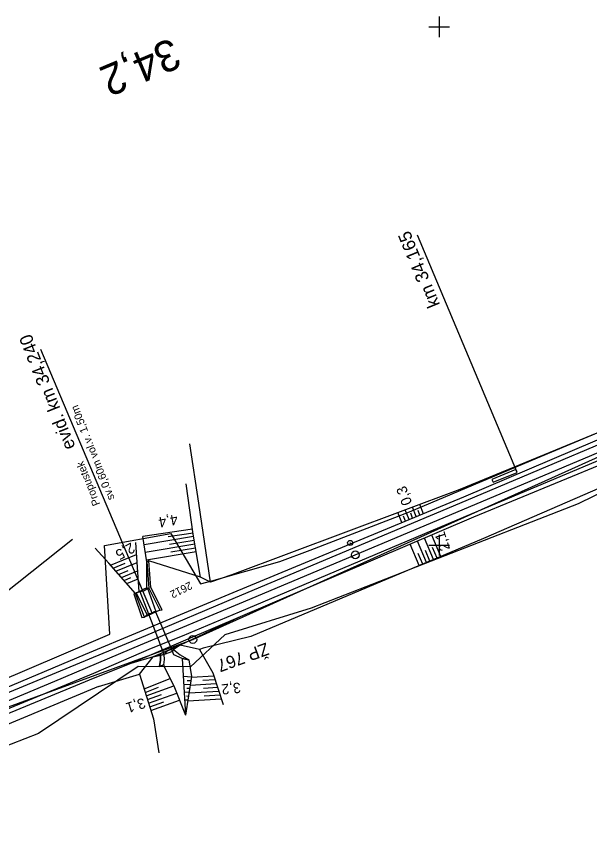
# Model space of a CAD drawing. Extents: x -805730 to -804640, y -1150889 to -1150366.
# Drawn here: x -805081.6 to -804971, y -1150657.1 to -1150498 of the extents above; entities that cross this region are included whole.
import ezdxf

# ---------------------------------------------------------------- set-up
doc = ezdxf.new("R2010")
doc.units = 0
for name, color, linetype in [('0381KM032-037P - Vrstva 1', 7, 'Continuous'), ('0381KM032-037P - Vrstva 16', 7, 'Continuous'), ('0381KM032-037P - Vrstva 17', 7, 'Continuous'), ('0381KM032-037P - Vrstva 19', 7, 'Continuous'), ('0381KM032-037P - Vrstva 4', 7, 'Continuous'), ('0381KM032-037P - Vrstva 48', 7, 'Continuous'), ('0381KM032-037P - Vrstva 49', 7, 'Continuous'), ('0381KM032-037P - Vrstva 57', 7, 'Continuous'), ('0381KM032-037P - Vrstva 7', 7, 'Continuous'), ('0381KM032-037P - Vrstva 9', 7, 'Continuous'), ('hran DP - hran DP', 7, 'Continuous'), ('krizky_1000 - Vrstva 1', 7, 'Continuous'), ('vyt_sit - polygon', 7, 'Continuous'), ('vyt_sit - stávající', 7, 'Continuous')]:
    doc.layers.add(name, color=color, linetype=linetype)

msp = doc.modelspace()

# ---------------------------------------------------------------- linework, layer by layer
at = {"layer": '0381KM032-037P - Vrstva 1'}
for points in [[(-804910.33, -1150557.31), (-804952.12, -1150574.92), (-804994.42, -1150592.71), (-805038.63, -1150611.27), (-805057.71, -1150619.3), (-805074.24, -1150626.27)], [(-805074.24, -1150626.27), (-805091.51, -1150633.48)]]:
    msp.add_lwpolyline(points, dxfattribs=at)
at = {"layer": '0381KM032-037P - Vrstva 16'}
for points in [[(-805053.78, -1150621.21), (-805053.78, -1150622.18), (-805053.99, -1150623.39), (-805053.13, -1150623.09), (-805053, -1150622.04), (-805053.1, -1150621.07), (-805053.78, -1150621.21)], [(-805051.5, -1150620.47), (-805051.28, -1150620.09), (-805050.01, -1150621.11), (-805048.33, -1150622.13), (-805049.58, -1150621.86), (-805051.2, -1150621.14), (-805051.5, -1150620.47)]]:
    msp.add_lwpolyline(points, dxfattribs=at)
at = {"layer": '0381KM032-037P - Vrstva 17'}
for points in [[(-804868.16, -1150549.89), (-804869.02, -1150549.09), (-804889.78, -1150557.12), (-804908.89, -1150563.18), (-804949.8, -1150580.61), (-804991.45, -1150598.69), (-805036.34, -1150617.58)], [(-804906.51, -1150551), (-804923.2, -1150557.6), (-804942.52, -1150566.83), (-804953.3, -1150571.71), (-804995.99, -1150589.23), (-805040.03, -1150605.68), (-805044.15, -1150607.13)], [(-805044.15, -1150607.13), (-805046.42, -1150591.86), (-805048.16, -1150580.41)], [(-805070.8, -1150598.9), (-805121.06, -1150638.84), (-805152.76, -1150646.7), (-805170.92, -1150650.08), (-805194.39, -1150650.05), (-805213.2, -1150651.26), (-805221.79, -1150652.33), (-805228.79, -1150654.03)]]:
    msp.add_lwpolyline(points, dxfattribs=at)
at = {"layer": '0381KM032-037P - Vrstva 19'}
for p, q in [((-805076.95, -1150562.18), (-805055.39, -1150613.19)), ((-805056.34, -1150613.34), (-805058.5, -1150609.19)), ((-805054.78, -1150612.85), (-805056.06, -1150613.31)), ((-805053.1, -1150621.07), (-805056.06, -1150613.31)), ((-805054.78, -1150612.85), (-805051.5, -1150620.47)), ((-805051.5, -1150620.47), (-805053.1, -1150621.07))]:
    msp.add_line(p, q, dxfattribs=at)
for points in [[(-805056.22, -1150608.31), (-805056.45, -1150608.2), (-805056.44, -1150603.21)], [(-805053.89, -1150612.54), (-805053.47, -1150612.44), (-805055.64, -1150608.13), (-805056.05, -1150602.98), (-805056.44, -1150603.21), (-805056.02, -1150608.26)], [(-805056.45, -1150608.2), (-805056.99, -1150608.48), (-805057.93, -1150608.98), (-805058.5, -1150609.19)], [(-805054.6, -1150612.84), (-805056.22, -1150608.31), (-805056.92, -1150608.82), (-805057.71, -1150609)], [(-805056.22, -1150608.31), (-805056.02, -1150608.26), (-805053.89, -1150612.54), (-805056.9, -1150613.84)], [(-805056.06, -1150613.31), (-805057.71, -1150609), (-805058.5, -1150609.19), (-805058.59, -1150609.33), (-805058.96, -1150609.37), (-805057.41, -1150613.95), (-805056.9, -1150613.84), (-805058.59, -1150609.33)], [(-805055.86, -1150613.18), (-805056.06, -1150613.31), (-805056.34, -1150613.34), (-805056.9, -1150613.84)], [(-805054.6, -1150612.84), (-805054.78, -1150612.85), (-805055.1, -1150612.83)], [(-805055.21, -1150621.51), (-805053.78, -1150621.21), (-805055.21, -1150621.51), (-805050.01, -1150619.25), (-805051.28, -1150620.09), (-805051.5, -1150620.47), (-805051.69, -1150620.12)], [(-805053.78, -1150621.21), (-805053.1, -1150621.07), (-805052.93, -1150620.83)]]:
    msp.add_lwpolyline(points, dxfattribs=at)
for centre, major_axis, ratio, start_param, end_param in [((-805055.48, -1150613.01), (0.389, 0.172), 0.155868, 3.060843, 6.493994), ((-805052.24, -1150620.62), (-0.751, -0.434), 0.315901, 3.723079, 5.657425)]:
    msp.add_ellipse(centre, major_axis=major_axis, ratio=ratio, start_param=start_param, end_param=end_param, dxfattribs=at)
at = {"layer": '0381KM032-037P - Vrstva 4'}
for points in [[(-804864.42, -1150538.53), (-804893.06, -1150548.77), (-804911.6, -1150556.2), (-804952.82, -1150573.68), (-804994.86, -1150591.44), (-805039.39, -1150610.13), (-805056.71, -1150617.44), (-805097.6, -1150634.39)], [(-804872.17, -1150539.66), (-804893.72, -1150547.52), (-804911.96, -1150555), (-804952.93, -1150572.63), (-804995.29, -1150590.69), (-805039.86, -1150609.18), (-805057.83, -1150616.69), (-805068.36, -1150621.07), (-805097.92, -1150633.57)], [(-804862.73, -1150542.41), (-804863.39, -1150541.46), (-804892.29, -1150551.48), (-804910.22, -1150558.86), (-804951.61, -1150576.23), (-804993.7, -1150593.96), (-805038.63, -1150612.92), (-805049.62, -1150617.53), (-805055.59, -1150619.94), (-805066.74, -1150624.75), (-805096.44, -1150637.01)], [(-804864.94, -1150543.15), (-804869.59, -1150544.8), (-804891.93, -1150552.26), (-804909.8, -1150559.87), (-804951.24, -1150577.2), (-804993.38, -1150594.6), (-805038.39, -1150613.8), (-805059.54, -1150622.79), (-805066.49, -1150625.57), (-805096.25, -1150637.87)]]:
    msp.add_lwpolyline(points, dxfattribs=at)
at = {"layer": '0381KM032-037P - Vrstva 48'}
for p, q in [((-805004.43, -1150594.48), (-805005.15, -1150592.66)), ((-805003.04, -1150593.91), (-805003.74, -1150592.13)), ((-805007.2, -1150595.63), (-805007.96, -1150593.7)), ((-805006.51, -1150595.34), (-805006.88, -1150594.39)), ((-805005.82, -1150595.05), (-805006.56, -1150593.18)), ((-805005.12, -1150594.77), (-805005.49, -1150593.84)), ((-805003.74, -1150594.19), (-805004.09, -1150593.29)), ((-805047.61, -1150596.92), (-805057.19, -1150598.31)), ((-805047.4, -1150598.32), (-805056.95, -1150599.89)), ((-805047.5, -1150597.67), (-805052.29, -1150598.36)), ((-805047.27, -1150599.06), (-805052.05, -1150599.84)), ((-805002.47, -1150603.33), (-805004.21, -1150599.21)), ((-805001.09, -1150602.75), (-805002.83, -1150598.63)), ((-804999.71, -1150602.17), (-805001.45, -1150598.04)), ((-805047.15, -1150599.8), (-805056.72, -1150601.37)), ((-805047.02, -1150600.54), (-805051.82, -1150601.32)), ((-805003.86, -1150603.91), (-805005.59, -1150599.8)), ((-805000.4, -1150602.46), (-805001.27, -1150600.4)), ((-805063.45, -1150603.82), (-805058.4, -1150601.75)), ((-805046.9, -1150601.28), (-805056.5, -1150602.85)), ((-805003.17, -1150603.62), (-805004.03, -1150601.56)), ((-805001.78, -1150603.04), (-805002.65, -1150600.98)), ((-805062.93, -1150604.42), (-805060.64, -1150603.48)), ((-805062.4, -1150605.02), (-805058.3, -1150603.33)), ((-805061.88, -1150605.61), (-805060.06, -1150604.86)), ((-805061.35, -1150606.21), (-805058.2, -1150604.91)), ((-805060.83, -1150606.8), (-805059.49, -1150606.25)), ((-805060.3, -1150607.4), (-805058.09, -1150606.49)), ((-805056.95, -1150627.71), (-805051.95, -1150625.67)), ((-805047.79, -1150625.42), (-805049.38, -1150625.34)), ((-805047.91, -1150626.17), (-805048.62, -1150626.13)), ((-805043.49, -1150625.24), (-805047.8, -1150625.5)), ((-805043.25, -1150625.97), (-805045.59, -1150626.11)), ((-805056.72, -1150628.43), (-805054.17, -1150627.38)), ((-805056.53, -1150629.02), (-805051.22, -1150627.12)), ((-805048.02, -1150626.91), (-805049.29, -1150626.85)), ((-805048.14, -1150627.66), (-805048.69, -1150627.63)), ((-805043.02, -1150626.71), (-805048.04, -1150627.02)), ((-805042.78, -1150627.45), (-805045.47, -1150627.61)), ((-805056.31, -1150629.74), (-805053.62, -1150628.78)), ((-805056.08, -1150630.46), (-805050.66, -1150628.52)), ((-805048.26, -1150628.4), (-805049.2, -1150628.36)), ((-805048.37, -1150629.15), (-805048.77, -1150629.13)), ((-805042.54, -1150628.18), (-805048.28, -1150628.53)), ((-805042.3, -1150628.92), (-805045.35, -1150629.11)), ((-805055.86, -1150631.17), (-805053.12, -1150630.19)), ((-805055.63, -1150631.89), (-805050.1, -1150629.91)), ((-805048.49, -1150629.89), (-805049.11, -1150629.86)), ((-805042.06, -1150629.66), (-805048.51, -1150630.05))]:
    msp.add_line(p, q, dxfattribs=at)
at = {"layer": '0381KM032-037P - Vrstva 49'}
for p, q in [((-805056.44, -1150603.21), (-805057.2, -1150598.28)), ((-805057.93, -1150608.98), (-805058.55, -1150599.44)), ((-805056.05, -1150602.98), (-805056.44, -1150603.21)), ((-805044.15, -1150607.13), (-805046.07, -1150606.17)), ((-805049.58, -1150621.86), (-805048.94, -1150632.8)), ((-805049.58, -1150621.86), (-805048.33, -1150622.13))]:
    msp.add_line(p, q, dxfattribs=at)
for points in [[(-804871.36, -1150538.86), (-804872.17, -1150539.66), (-804893.72, -1150547.52), (-804911.96, -1150555), (-804952.93, -1150572.63), (-804995.29, -1150590.69), (-805039.86, -1150609.18), (-805057.83, -1150616.69), (-805068.36, -1150621.07), (-805097.92, -1150633.57)], [(-804906.51, -1150551), (-804923.2, -1150557.6), (-804942.52, -1150566.83), (-804953.3, -1150571.71), (-804995.99, -1150589.23), (-805040.03, -1150605.68), (-805044.15, -1150607.13)], [(-804889.78, -1150557.12), (-804908.89, -1150563.18), (-804949.8, -1150580.61), (-804991.45, -1150598.69), (-805036.34, -1150617.58)], [(-804909.8, -1150559.87), (-804951.24, -1150577.2), (-804993.38, -1150594.6), (-805038.39, -1150613.8), (-805050.01, -1150619.25), (-805055.21, -1150621.51), (-805059.54, -1150622.79), (-805066.49, -1150625.57), (-805096.25, -1150637.87)], [(-805046.07, -1150606.17), (-805047.47, -1150597.89), (-805048.87, -1150588.15)], [(-805070.8, -1150598.9), (-805121.06, -1150638.84), (-805152.76, -1150646.7), (-805170.92, -1150650.08), (-805194.39, -1150650.05), (-805213.2, -1150651.26), (-805221.79, -1150652.33), (-805228.79, -1150654.03)], [(-805058.59, -1150609.33), (-805063.79, -1150603.44), (-805066.42, -1150600.59)], [(-805046.07, -1150606.17), (-805056.05, -1150602.98)], [(-805058.59, -1150609.33), (-805058.5, -1150609.19), (-805057.93, -1150608.98)], [(-805036.34, -1150617.58), (-805045.56, -1150619.85), (-805046.28, -1150620.1), (-805050.01, -1150619.25)], [(-805065.73, -1150627.22), (-805057.84, -1150624.88), (-805055.21, -1150621.51)], [(-805053.13, -1150623.09), (-805053.99, -1150623.39), (-805053.78, -1150622.18), (-805053.78, -1150621.21), (-805055.21, -1150621.51)], [(-805046.28, -1150620.1), (-805043.7, -1150624.61), (-805041.72, -1150630.72)], [(-805053.13, -1150623.09), (-805053.07, -1150623.46), (-805051.23, -1150627.1), (-805048.94, -1150632.8)], [(-805048.33, -1150622.13), (-805047.78, -1150625.31), (-805048.94, -1150632.8)], [(-805057.84, -1150624.88), (-805055.13, -1150633.48), (-805054.13, -1150640.03)], [(-805065.73, -1150627.22), (-805095.53, -1150639.67)]]:
    msp.add_lwpolyline(points, dxfattribs=at)
at = {"layer": '0381KM032-037P - Vrstva 7'}
msp.add_line((-805017.22, -1150599.55), (-805017.12, -1150599.55), dxfattribs=at)
for centre, radius in [((-805017.17, -1150599.55), 0.5), ((-805016.2, -1150601.85), 0.75)]:
    msp.add_circle(centre, radius, dxfattribs=at)
at = {"layer": '0381KM032-037P - Vrstva 9'}
for p, q in [((-805004.24, -1150540.13), (-804985.09, -1150585.68)), ((-804985.2, -1150585.4), (-804985.43, -1150584.85)), ((-804985.2, -1150585.4), (-804989.83, -1150587.31)), ((-804989.6, -1150587.86), (-804984.97, -1150585.96)), ((-804984.97, -1150585.96), (-804985.2, -1150585.4)), ((-804989.83, -1150587.31), (-804989.6, -1150587.86))]:
    msp.add_line(p, q, dxfattribs=at)
at = {"layer": 'hran DP - hran DP'}
for p, q in [((-804981, -1150583.16), (-804968.41, -1150577.86)), ((-804951.89, -1150581.61), (-804973.16, -1150591.99)), ((-804993.4, -1150588.37), (-804981, -1150583.16)), ((-805005.74, -1150593.57), (-804993.4, -1150588.37)), ((-804973.16, -1150591.99), (-805001.53, -1150603.08)), ((-805024.92, -1150600.92), (-805005.74, -1150593.57)), ((-805064.61, -1150600.03), (-805051.81, -1150597.72)), ((-805051.81, -1150597.72), (-805046.06, -1150607.46)), ((-805063.58, -1150617.18), (-805064.61, -1150600.03)), ((-805030.76, -1150603.16), (-805024.92, -1150600.92)), ((-805043.88, -1150606.84), (-805030.76, -1150603.16)), ((-805001.53, -1150603.08), (-805004.51, -1150604.24)), ((-805006.96, -1150605.2), (-805008.86, -1150605.94)), ((-805004.51, -1150604.24), (-805006.96, -1150605.2)), ((-805046.06, -1150607.46), (-805043.88, -1150606.84)), ((-805008.86, -1150605.94), (-805024.72, -1150612.14)), ((-805024.72, -1150612.14), (-805041.4, -1150617.28)), ((-805066.7, -1150618.51), (-805063.58, -1150617.18)), ((-805041.4, -1150617.28), (-805048.02, -1150623.43)), ((-805096.7, -1150631.27), (-805066.7, -1150618.51)), ((-805058.1, -1150623.37), (-805077.33, -1150636.32)), ((-805048.02, -1150623.43), (-805058.1, -1150623.37)), ((-805077.33, -1150636.32), (-805095.21, -1150643.26))]:
    msp.add_line(p, q, dxfattribs=at)
at = {"layer": 'krizky_1000 - Vrstva 1'}
for points in [[(-805000, -1150498), (-805000, -1150502)], [(-805002, -1150500), (-804998, -1150500)], [(-805000, -1150598), (-805000, -1150602)], [(-805002, -1150600), (-804998, -1150600)]]:
    msp.add_lwpolyline(points, dxfattribs=at)
at = {"layer": 'vyt_sit - polygon'}
for p, q in [((-805047.55, -1150618.19), (-804870.84, -1150538.58)), ((-805154.33, -1150657.15), (-805047.55, -1150618.19))]:
    msp.add_line(p, q, dxfattribs=at)
at = {"layer": 'vyt_sit - stávající'}
msp.add_line((-805047.59, -1150618.19), (-805047.49, -1150618.19), dxfattribs=at)
msp.add_circle((-805047.55, -1150618.19), 0.756, dxfattribs=at)

# ---------------------------------------------------------------- texts
at = {"layer": '0381KM032-037P - Vrstva 19'}
for s, height, p in [('evid. km 34,240', 2.5, (-805070.16, -1150581.01)), ('sv.0,60m vol.v. 1,50m', 1.5, (-805062.62, -1150590.96)), ('Propustek', 1.5, (-805065.41, -1150592.06))]:
    msp.add_text(s, height=height, rotation=111.5275, dxfattribs=at).set_placement(p)
at = {"layer": '0381KM032-037P - Vrstva 48'}
for s, rotation, p in [('0,3', 110.4812, (-805005.19, -1150591.87)), ('4,4', 189.5991, (-805050.63, -1150594.02)), ('2,1', 108.1045, (-804997.87, -1150600.72)), ('2,5', 208.7064, (-805059.44, -1150599.4)), ('3,2', 186.1394, (-805038.41, -1150626.45)), ('3,1', 197.4468, (-805057.08, -1150629.39))]:
    msp.add_text(s, height=2, rotation=rotation, dxfattribs=at).set_placement(p)
at = {"layer": '0381KM032-037P - Vrstva 57'}
msp.add_text('2612', height=1.5, rotation=206.8307, dxfattribs=at).set_placement((-805048.13, -1150606.95))
at = {"layer": '0381KM032-037P - Vrstva 7'}
msp.add_text('34,2', height=6, rotation=202.7734, dxfattribs=at).set_placement((-805051.6, -1150502))
at = {"layer": '0381KM032-037P - Vrstva 9'}
msp.add_text('km 34,165', height=2.5, rotation=112.3772, dxfattribs=at).set_placement((-804999.79, -1150553.58))
at = {"layer": 'vyt_sit - stávající'}
msp.add_text('ŽP 767', height=2.4, rotation=200, dxfattribs=at).set_placement((-805033.38, -1150618.73))

doc.saveas('drawing.dxf')
